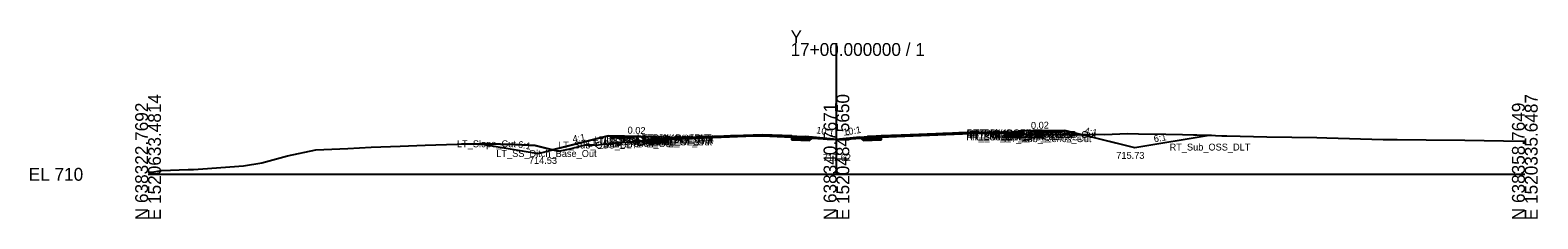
# Model space of a CAD drawing. Extents: x -26 to 303, y -10 to 5039.
# Drawn here: x -25.7 to 302.8, y 490.3 to 531.4 of the extents above; entities that cross this region are included whole.
import ezdxf

# ---------------------------------------------------------------- set-up
doc = ezdxf.new("R2010")
doc.units = 0
for name, color, linetype in [('Default', 7, 'Continuous'), ('Exist Cross Section Cell', 7, 'Continuous'), ('Exist XS Center Line Elevation Label', 7, 'Continuous'), ('Exist XS Ground Line', 7, 'Continuous'), ('Prop CMT Pvmt Course 1', 7, 'Continuous'), ('Prop CMT Pvmt Course 2', 7, 'Continuous'), ('Prop CMT Pvmt Course 3', 7, 'Continuous'), ('Prop CMT Pvmt Surface', 7, 'Continuous'), ('Prop CMT Pvmt Surface Shoulder', 7, 'Continuous'), ('Prop CMT Shld Paved Course 1', 7, 'Continuous'), ('Prop CMT Shld Paved Course 2', 7, 'Continuous'), ('Prop CMT Shld Paved Course 3', 7, 'Continuous'), ('Prop CMT Slope Grass', 7, 'Continuous'), ('Prop CMT Subgrade Earthwork', 7, 'Continuous'), ('Prop Conc 4in Sidewalk', 7, 'Continuous'), ('Prop XS Ditch Standard Text', 7, 'Continuous'), ('Prop XS Earthwork Shape', 7, 'Continuous'), ('Prop XS Side Slope Text', 7, 'Continuous'), ('Scratch_Level_0', 7, 'Continuous'), ('Typical Curb CELL', 7, 'Continuous'), ('Typical Shoulder Slope Information CELL', 7, 'Continuous')]:
    doc.layers.add(name, color=color, linetype=linetype)

# ---------------------------------------------------------------- blocks, each defined once
blk = doc.blocks.new('2_6 CURB RIGHT')
at = {"layer": 'Typical Curb CELL'}
for p, q in [((0, -0.58), (0, 0)), ((0, 0), (1.75, -0.07)), ((2, 0.17), (2, 0.18)), ((2.5, 0.42), (2.24, 0.42)), ((2.31, 0.08), (2.33, -0.01)), ((2.46, 0.04), (2.31, 0.08)), ((2.33, -0.01), (2.46, 0.04)), ((2.5, -0.58), (2.5, 0.42)), ((2.5, -0.58), (0, -0.58)), ((0.26, -0.34), (0.35, -0.22)), ((0.38, -0.34), (0.26, -0.34)), ((0.35, -0.22), (0.38, -0.34)), ((1.03, -0.39), (1.09, -0.28)), ((1.19, -0.36), (1.03, -0.39)), ((1.09, -0.28), (1.19, -0.36)), ((1.51, -0.34), (1.6, -0.22)), ((1.63, -0.34), (1.51, -0.34)), ((1.6, -0.22), (1.63, -0.34)), ((2.27, -0.39), (2.34, -0.28)), ((2.44, -0.36), (2.27, -0.39)), ((2.34, -0.28), (2.44, -0.36))]:
    blk.add_line(p, q, dxfattribs=at)
for centre in [(2.27, 0.34), (2.43, 0.12), (2.49, 0.31), (0.01, -0.55), (0.02, -0.25), (0.03, -0.15), (0.07, -0.39), (0.09, -0.18), (0.17, -0.34), (0.2, -0.06), (0.22, -0.58), (0.3, -0.14), (0.34, -0.04), (0.38, -0.51), (0.49, -0.1), (0.52, -0.21), (0.59, -0.53), (0.67, -0.29), (0.69, -0.12), (0.7, -0.45), (0.71, -0.07), (0.76, -0.56), (0.79, -0.26), (0.93, -0.5), (0.97, -0.1), (1.09, -0.15), (1.11, -0.54), (1.26, -0.55), (1.27, -0.25), (1.28, -0.15), (1.32, -0.39), (1.34, -0.18), (1.42, -0.34), (1.45, -0.1), (1.47, -0.58), (1.54, -0.14), (1.63, -0.51), (1.74, -0.1), (1.77, -0.21), (1.84, -0.53), (1.92, -0.29), (1.94, -0.12), (1.95, -0.45), (1.96, -0.07), (2.01, -0.56), (2.04, -0.26), (2.18, -0.5), (2.22, -0.1), (2.34, -0.15), (2.35, -0.54)]:
    blk.add_circle(centre, 0.00802, dxfattribs=at)
for centre, start, end in [((1.76, 0.17), 267.6155, 0), ((2.24, 0.18), 90, 180)]:
    blk.add_arc(centre, 0.24, start, end, dxfattribs=at)

msp = doc.modelspace()

# ---------------------------------------------------------------- linework, layer by layer
at = {"layer": 'Exist Cross Section Cell'}
for p, q in [((150, 500), (150, 528.58)), ((0, 500), (150, 500)), ((150, 500), (300, 500))]:
    msp.add_line(p, q, dxfattribs=at)
at = {"layer": 'Exist XS Ground Line'}
msp.add_lwpolyline([(0, 500.5), (1.33, 500.55), (2.92, 500.8), (8.71, 501.04), (9.9, 501.05), (10.9, 501.13), (11.94, 501.19), (20.78, 501.84), (24.79, 502.47), (30.37, 504.03), (36.58, 505.31), (43.5, 505.63), (48.62, 505.88), (54.91, 506.12), (60.41, 506.38), (67.36, 506.57), (68.29, 506.6), (73.61, 506.65), (79.98, 506.47), (84.36, 506.28), (86.36, 505.74), (89.48, 505.03), (91.88, 505.57), (95.29, 506.4), (97.22, 506.4), (97.71, 506.38), (98.62, 506.48), (99.15, 506.55), (100.29, 506.65), (101.32, 506.74), (102.69, 506.87), (103.33, 506.93), (104.9, 507.07), (105.35, 507.1), (107.04, 507.26), (107.85, 507.34), (108.9, 507.45), (110.41, 507.6), (111.56, 507.72), (112.92, 507.84), (114.63, 507.98), (115.44, 507.98), (116.05, 508), (117.96, 508.04), (118.3, 508.05), (120.56, 508.14), (121.2, 508.16), (123.23, 508.23), (125.49, 508.32), (125.84, 508.33), (126.89, 508.37), (127.51, 508.37), (128, 508.36), (129.52, 508.36), (130.53, 508.35), (131.75, 508.36), (133.03, 508.36), (134.01, 508.35), (135.58, 508.35), (137.49, 508.34), (138.01, 508.34), (138.77, 508.33), (139.09, 508.32), (139.45, 508.29), (142.61, 508.03), (147.1, 507.71), (147.97, 507.65), (150, 507.62), (151.43, 507.65), (153.2, 507.75), (157.32, 507.98), (159.19, 508.17), (161.82, 508.45), (162.43, 508.47), (163.28, 508.5), (165.48, 508.59), (165.79, 508.6), (167.74, 508.69), (168.33, 508.72), (169.98, 508.79), (170.84, 508.82), (173.21, 508.95), (173.73, 508.97), (175.85, 508.99), (176.68, 509), (178.37, 509.02), (180.5, 509.02), (180.89, 509.02), (181.19, 509.02), (183.51, 509.03), (185.63, 509.04), (186.07, 509.01), (188.07, 508.91), (192.08, 508.72), (195.74, 508.65), (198.42, 508.66), (202.59, 508.65), (206.46, 508.71), (208.38, 508.69), (213.41, 508.85), (215.79, 508.83), (221.77, 508.74), (225.43, 508.7), (232.61, 508.47), (233.95, 508.4), (235.06, 508.38), (243.81, 508.17), (254.71, 507.98), (256.88, 507.93), (269.11, 507.61), (272.15, 507.55), (278.53, 507.49), (286.95, 507.41), (299.55, 507.23), (300, 507.22)], dxfattribs=at)
at = {"layer": 'Prop CMT Pvmt Course 1'}
for points in [[(113.25, 507.8), (113.25, 507.55)], [(113.25, 507.55), (113.26, 507.55)], [(113.26, 507.55), (113.26, 507.8)], [(113.99, 507.68), (114, 507.68)], [(139.01, 508.28), (139.02, 508.28)], [(140.25, 508.11), (140.25, 508.36)], [(159.75, 508.11), (159.75, 508.36)], [(161.79, 508.44), (161.79, 508.19)], [(161.79, 508.19), (161.8, 508.19)], [(186.74, 508.73), (186.74, 508.98)]]:
    msp.add_lwpolyline(points, dxfattribs=at)
at = {"layer": 'Prop CMT Pvmt Course 2'}
for points in [[(113.26, 507.55), (113.25, 507.55)], [(113.25, 507.55), (113.25, 507.3)], [(113.25, 507.3), (113.26, 507.3)], [(113.26, 507.3), (113.26, 507.55)], [(114, 507.68), (113.99, 507.68)], [(140.25, 507.86), (140.25, 508.11)], [(159.75, 507.86), (159.75, 508.11)], [(161.8, 508.19), (161.79, 508.19)]]:
    msp.add_lwpolyline(points, dxfattribs=at)
at = {"layer": 'Prop CMT Pvmt Course 3'}
for points in [[(113.26, 507.3), (113.25, 507.3)], [(113.25, 507.3), (113.25, 506.92)], [(113.26, 506.92), (113.26, 507.3)], [(140.25, 507.49), (140.25, 507.86)], [(140.26, 507.49), (140.25, 507.49)], [(159.74, 507.49), (159.75, 507.49)], [(159.75, 507.49), (159.75, 507.86)]]:
    msp.add_lwpolyline(points, dxfattribs=at)
at = {"layer": 'Prop CMT Pvmt Surface'}
msp.add_lwpolyline([(139.01, 508.28), (139.02, 508.28)], dxfattribs=at)
at = {"layer": 'Prop CMT Pvmt Surface Shoulder'}
for points in [[(133.92, 508.62), (112.25, 507.75)], [(133.92, 508.62), (143.25, 508.24)], [(181.02, 509.21), (156.75, 508.24)], [(181.02, 509.21), (187.75, 508.94)]]:
    msp.add_lwpolyline(points, dxfattribs=at)
at = {"layer": 'Prop CMT Shld Paved Course 1'}
for p, q in [((133.92, 508.37), (112.26, 507.5)), ((133.92, 508.37), (140.25, 508.11)), ((143.51, 507.98), (143.25, 508.24)), ((156.75, 508.24), (156.49, 507.98))]:
    msp.add_line(p, q, dxfattribs=at)
for points in [[(112.25, 507.51), (113.26, 507.55)], [(113.25, 507.55), (113.25, 507.8)], [(159.56, 508.1), (181.02, 508.96)], [(161.79, 508.19), (161.79, 508.44)], [(186.01, 509.01), (187.75, 508.94)], [(187.75, 508.69), (186.75, 508.73)]]:
    msp.add_lwpolyline(points, dxfattribs=at)
at = {"layer": 'Prop CMT Shld Paved Course 2'}
for p, q in [((143.77, 507.72), (143.51, 507.98)), ((156.23, 507.72), (156.49, 507.98))]:
    msp.add_line(p, q, dxfattribs=at)
for points in [[(113.26, 507.55), (112.25, 507.51)], [(112.25, 507.26), (113.26, 507.3)], [(113.25, 507.3), (113.25, 507.55)], [(140.25, 508.11), (143.51, 507.98)], [(143.77, 507.72), (140.25, 507.86)], [(156.23, 507.72), (159.75, 507.86)], [(159.75, 508.11), (156.49, 507.98)], [(186.75, 508.73), (187.75, 508.69)], [(187.75, 508.44), (186.75, 508.48)]]:
    msp.add_lwpolyline(points, dxfattribs=at)
at = {"layer": 'Prop CMT Shld Paved Course 3'}
for p, q in [((109.25, 507.17), (108.82, 506.74)), ((109.75, 507.17), (109.25, 507.17)), ((144.16, 507.33), (143.77, 507.72)), ((155.84, 507.33), (156.23, 507.72))]:
    msp.add_line(p, q, dxfattribs=at)
for points in [[(108.82, 506.74), (113.26, 506.92)], [(113.26, 507.3), (112.25, 507.26)], [(113.25, 506.92), (113.25, 507.3)], [(140.25, 507.86), (143.77, 507.72)], [(144.16, 507.33), (140.25, 507.49)], [(155.84, 507.33), (159.75, 507.49)], [(159.75, 507.86), (156.23, 507.72)], [(191.18, 507.93), (186.74, 508.11)], [(186.75, 508.48), (187.75, 508.44)], [(191.18, 507.93), (186.75, 508.11)]]:
    msp.add_lwpolyline(points, dxfattribs=at)
at = {"layer": 'Prop CMT Slope Grass'}
for p, q in [((199.75, 509.55), (190.25, 509.36)), ((215.03, 505.73), (199.75, 509.55)), ((72.36, 506.64), (84.97, 504.53)), ((84.97, 504.53), (100.25, 508.36)), ((100.25, 508.36), (109.75, 508.17)), ((150, 507.57), (143.25, 508.24)), ((150, 507.57), (156.75, 508.24)), ((231.65, 508.5), (215.03, 505.73))]:
    msp.add_line(p, q, dxfattribs=at)
at = {"layer": 'Prop CMT Subgrade Earthwork'}
for p, q in [((191.18, 507.93), (192.65, 509.41)), ((108.82, 506.74), (107.35, 508.22)), ((113.26, 506.92), (113.26, 507.79)), ((140.25, 508.36), (140.25, 507.49)), ((159.75, 508.36), (159.75, 507.49))]:
    msp.add_line(p, q, dxfattribs=at)
for points in [[(113.26, 506.92), (108.82, 506.74)], [(140.25, 508.36), (140.25, 507.49), (140.26, 507.49)], [(140.25, 507.49), (144.16, 507.33)], [(144.16, 507.33), (144.91, 508.08)], [(155.84, 507.33), (155.09, 508.08)], [(159.75, 507.49), (155.84, 507.33)], [(159.75, 508.36), (159.75, 507.49), (159.74, 507.49)], [(186.74, 508.98), (186.74, 508.11)], [(186.74, 508.11), (191.18, 507.93)]]:
    msp.add_lwpolyline(points, dxfattribs=at)
at = {"layer": 'Prop Conc 4in Sidewalk'}
for p, q in [((194.25, 509.44), (194.25, 509.11)), ((199.25, 509.54), (199.25, 509.21)), ((100.75, 508.35), (100.75, 508.01)), ((100.75, 508.01), (105.75, 507.91)), ((105.75, 508.25), (105.75, 507.91)), ((199.25, 509.21), (194.25, 509.11))]:
    msp.add_line(p, q, dxfattribs=at)
at = {"layer": 'Prop XS Earthwork Shape'}
for points in [[(191.97, 508.73), (192.65, 509.41), (199.75, 509.55), (203.31, 508.66), (202.59, 508.65), (198.42, 508.66), (195.74, 508.65), (192.08, 508.72)], [(72.36, 506.64), (84.97, 504.53), (88.15, 505.33), (86.36, 505.74), (84.36, 506.28), (79.98, 506.47), (73.61, 506.65)], [(102.69, 506.87), (103.33, 506.93), (104.9, 507.07), (105.35, 507.1), (107.04, 507.26), (107.85, 507.34), (108.19, 507.38), (107.35, 508.21), (100.25, 508.36), (88.15, 505.33), (89.48, 505.03), (91.88, 505.57), (95.29, 506.4), (97.22, 506.4), (97.71, 506.38), (98.62, 506.48), (99.15, 506.55), (100.29, 506.65), (101.32, 506.74)], [(108.82, 506.74), (108.19, 507.38), (108.9, 507.45), (110.41, 507.6), (111.56, 507.72), (112.14, 507.77), (112.25, 507.75), (113.26, 507.79), (113.26, 506.92)], [(112.14, 507.77), (112.25, 507.75), (113.26, 507.79), (127.7, 508.37), (127.51, 508.37), (126.89, 508.37), (125.84, 508.33), (125.49, 508.32), (123.23, 508.23), (121.2, 508.16), (120.56, 508.14), (118.3, 508.05), (117.96, 508.04), (116.05, 508), (115.44, 507.98), (114.63, 507.98), (112.92, 507.84)], [(134.01, 508.35), (135.58, 508.35), (137.49, 508.34), (138.01, 508.34), (138.77, 508.33), (139.09, 508.32), (139.45, 508.29), (140.25, 508.23), (140.25, 508.36), (133.92, 508.62), (127.7, 508.37), (128, 508.36), (129.52, 508.36), (130.53, 508.35), (131.75, 508.36), (133.03, 508.36)], [(144.16, 507.33), (144.71, 507.88), (142.61, 508.03), (140.25, 508.23), (140.26, 507.49)], [(147.1, 507.71), (147.97, 507.65), (149.39, 507.63), (144.91, 508.08), (144.71, 507.88)], [(150, 507.57), (149.39, 507.63), (150, 507.62), (150.68, 507.64)], [(150.68, 507.64), (151.43, 507.65), (153.2, 507.75), (155.31, 507.86), (155.09, 508.08)], [(155.84, 507.33), (155.31, 507.86), (157.32, 507.98), (159.19, 508.17), (159.75, 508.23), (159.74, 507.49)], [(159.75, 508.36), (159.75, 508.23), (161.82, 508.45)], [(162.43, 508.47), (163.28, 508.5), (165.48, 508.59), (165.79, 508.6), (166.15, 508.62), (162.01, 508.45)], [(166.15, 508.62), (167.74, 508.69), (168.33, 508.72), (169.98, 508.79), (170.84, 508.82), (173.21, 508.95), (173.73, 508.97), (175.27, 508.98)], [(181.02, 509.21), (185.48, 509.03), (183.51, 509.03), (181.19, 509.02), (180.89, 509.02), (180.5, 509.02), (178.37, 509.02), (176.68, 509), (175.85, 508.99), (175.27, 508.98)], [(185.48, 509.03), (185.97, 509.02), (185.63, 509.04)], [(185.97, 509.02), (186.74, 508.98), (186.07, 509.01)], [(186.74, 508.98), (188.07, 508.91), (191.97, 508.73), (191.18, 507.93), (186.74, 508.11)], [(231.65, 508.5), (215.03, 505.73), (203.31, 508.66), (206.46, 508.71), (208.38, 508.69), (213.41, 508.85), (215.79, 508.83), (221.77, 508.74), (225.43, 508.7)]]:
    msp.add_lwpolyline(points, close=True, dxfattribs=at)

# ---------------------------------------------------------------- block references
at = {"layer": 'Prop CMT Slope Grass'}
msp.add_blockref('2_6 CURB RIGHT', (187.75, 508.94), dxfattribs=at)
at = {"layer": 'Prop CMT Slope Grass', "yscale": -1, "rotation": 180}
msp.add_blockref('2_6 CURB RIGHT', (112.25, 507.75), dxfattribs=at)

# ---------------------------------------------------------------- texts
at = {"layer": 'Default'}
msp.add_text('-', height=0.0001, dxfattribs=at).set_placement((0, 500))
at = {"layer": 'Exist Cross Section Cell'}
for s, p in [('Y', (140, 528.58)), ('17+00.000000 / 1', (140, 525.78)), ('EL 710', (-26, 498.6))]:
    msp.add_text(s, height=2.8, dxfattribs=at).set_placement(p)
for s, p in [('E 1520633.4814', (2.8, 490)), ('E 1520484.5650', (152.8, 490)), ('E 1520335.6487', (302.8, 490)), ('N 638322.7692', (0, 490)), ('N 638340.7671', (150, 490)), ('N 638358.7649', (300, 490))]:
    msp.add_text(s, height=2.8, rotation=90, dxfattribs=at).set_placement(p)
at = {"layer": 'Exist XS Center Line Elevation Label'}
msp.add_text('717.62', height=1.5, dxfattribs=at).set_placement((147.02, 502.87))
at = {"layer": 'Prop XS Ditch Standard Text'}
for s, p in [('714.53', (82.98, 502.28)), ('715.73', (210.98, 503.36))]:
    msp.add_text(s, height=1.5, dxfattribs=at).set_placement(p)
at = {"layer": 'Prop XS Side Slope Text'}
for s, rotation, p in [('10:1', 350.5377, (145.51, 508.94)), ('10:1', 9.4623, (151.61, 508.4)), ('4:1', 346.7942, (203.91, 508.85)), ('6:1', 350.5191, (80.53, 505.82)), ('4:1', 9.4623, (92.63, 506.93)), ('6:1', 9.4809, (219.26, 506.97))]:
    msp.add_text(s, height=1.5, rotation=rotation, dxfattribs=at).set_placement(p)
at = {"layer": 'Scratch_Level_0'}
for s, p in [('RT_PV2_PGL_Out', (178.27, 508.01)), ('RT_PV3_PGL_Out', (178.27, 507.76)), ('RT_Sub_Out_DLT', (178.37, 508.26)), ('RT_PV1_PGL_Out', (178.45, 508.26)), ('RT_PV2_OEOT', (179.54, 508.01)), ('RT_PV3_OEOT', (179.54, 507.76)), ('RT_PV1_OEOT', (179.72, 508.26)), ('RT_SS_Ditch_Base_Out', (184.41, 507.92)), ('RT_PS1_OEOP', (187.78, 507.94)), ('RT_Slope_Cut', (188.53, 507.92)), ('LT_Slope_Cut', (67.31, 505.9)), ('LT_Sub_OSS_DLT', (89.35, 505.63)), ('LT_Sub_Trench_Out', (95.74, 505.93)), ('LT_PS3_Shelf_Out', (96.95, 506.32)), ('LT_GS_OS_CTL', (97.19, 506.78)), ('LT_PS3_OEOP', (99.15, 506.34)), ('LT_PS2_OEOP', (99.41, 506.6)), ('LT_PS1_OEOP', (99.85, 506.86)), ('LT_PV2_PGL_Out', (106.36, 506.93)), ('LT_PV3_PGL_Out', (106.36, 506.68)), ('LT_Sub_PGL_Out', (106.4, 506.3)), ('LT_Sub_Out_DLT', (106.49, 507.18)), ('LT_PV1_PGL_Out', (106.54, 507.18)), ('LT_PV2_OEOT', (107.61, 506.93)), ('LT_PV3_OEOT', (107.61, 506.68)), ('LT_Sub_OEOT', (107.64, 506.3)), ('LT_PV1_OEOT', (107.79, 507.18)), ('RT_Sub_PGL_Out', (178.31, 507.39)), ('RT_Sub_OEOT', (179.57, 507.39)), ('RT_Sub_Trench_Out', (186.5, 507.01)), ('RT_PS3_Shelf_Out', (186.93, 507.4)), ('RT_PS2_OEOP', (187.86, 507.68)), ('RT_PS3_OEOP', (188.12, 507.42)), ('RT_Sub_OSS_DLT', (222.59, 505.18)), ('LT_SS_Ditch_Base_Out', (75.88, 503.78))]:
    msp.add_text(s, height=1.5, dxfattribs=at).set_placement(p)
at = {"layer": 'Typical Shoulder Slope Information CELL'}
for rotation, p in [(358.8597, (104.48, 508.86)), (1.1403, (192.4, 509.89))]:
    msp.add_text('0.02', height=1.5, rotation=rotation, dxfattribs=at).set_placement(p)

doc.saveas('drawing.dxf')
